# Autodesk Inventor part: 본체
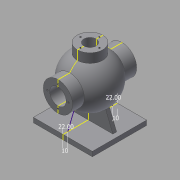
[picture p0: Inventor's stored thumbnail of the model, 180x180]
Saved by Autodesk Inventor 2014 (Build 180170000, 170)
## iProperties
Created: 2015-10
Part Number: 본체
Material: Generic
Document SubType Name: Modeling
Designer: youjin10
Density: 1 g/cm^3
Appearance: Default
Author: youjin10
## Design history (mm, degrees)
sketch "Sketch1"
  geometry: L1 (62.5, -57.5)-(-62.5, -57.5); L2 (-62.5, -57.5)-(-62.5, 57.5); L3 (-62.5, 57.5)-(62.5, 57.5); L4 (62.5, 57.5)-(62.5, -57.5); L5 (62.5, -57.5)-(-62.5, 57.5); L6 (-62.5, -57.5)-(62.5, 57.5); 1 further point
  constraints: 12 end point, 2 midpoint, 2 parallel, 1 horizontal, 1 perpendicular
  dimensions: "d0" = 125 distance of L2.end L3.end; "d1" = 115 distance of L1.end L2.end
extrude "Extrusion1" new body sketch "Sketch1" distance "d2" = 10; taper "d3" = 0 deg
workplane "Work Plane1"
sketch "Sketch4"
  geometry: L1 (0, 53)-(0, -53); L2 (8.646, -43.503)-(8.646, 43.503); A1 r 53 centre (0, 0) between (0, -53) and (0, 53); A2 r 44.354 centre (0, 0) between (8.646, -43.503) and (8.646, 43.503); 2 further points
  constraints: 4 end point, 4 point on circle, 2 centre point, 1 coincident, 1 midpoint, 1 vertical, 1 other
  dimensions: "d9" = 106 distance of L1.start L1.end; "d10" = 53 radius of A1
revolve "Revolution1" stored, may be unused: angle "d11" = 180 deg
workplane "Work Plane2"
sketch "Sketch6"
  geometry: C1 r 31 at (0, 85); 1 further point
  constraints: 1 centre point, 1 vertical alignment
  dimensions: "d13" = 62 diameter of C1; "d14" = 85 distance of point (0, 0) C1.centre
extrude "Extrusion2" join sketch "Sketch6" stored distance "d15" = 10; taper "d16" = 0 deg
mirror "Mirror1"
sketch "Sketch9"
  geometry: C1 r 31 at (0, 0) reference; C2 r 17.5 at (0, 0); 1 further point
  constraints: 1 centre point, 1 coincident
  dimensions: "d20" = 35 diameter of C2
extrude "Extrusion3" cut sketch "Sketch9" distance "d21" = 16; taper "d22" = 0 deg
sketch "Sketch10"
  geometry: C1 r 17.5 at (0, 0) reference; C2 r 18.5 at (0, 0); 1 further point
  constraints: 1 centre point, 1 coincident
  dimensions: "d23" = 37 diameter of C2
extrude "Extrusion4" cut sketch "Sketch10" distance "d24" = 1.75; taper "d25" = 0 deg
sketch "Sketch11"
  geometry: C1 r 18.5 at (0, 0) reference; C2 r 17.5 at (0, 0); 1 further point
  constraints: 1 centre point, 1 coincident
  dimensions: "d26" = 35 diameter of C2
extrude "Extrusion5" cut sketch "Sketch11" stored distance "d27" = 1.75; taper "d28" = 0 deg
workplane "Work Plane3"
sketch "Sketch12"
  geometry: C1 r 27 at (0, 0); 1 further point
  constraints: 1 centre point, 1 coincident
  dimensions: "d30" = 54 diameter of C1
extrude "Extrusion6" join sketch "Sketch12" stored distance "d31" = 1.75; taper "d32" = 0 deg
sketch "Sketch13"
  geometry: C1 r 27 at (0, 0) reference; C2 r 13 at (0, 0)
  constraints: 1 centre point, 1 coincident
  dimensions: "d33" = 26 diameter of C2
extrude "Extrusion7" cut sketch "Sketch13" distance "d34" = 50; taper "d35" = 0 deg
sketch "Sketch14"
  geometry: C1 r 17.5 at (0, 0) reference; C2 r 31 at (0, 0) reference; A1 r 22.5 centre (0, 0) between (0, 22.5) and (-22.5, 0); 3 further points
  constraints: 4 point on circle, 2 horizontal alignment, 2 vertical alignment, 1 centre point, 1 coincident
  dimensions: "d36" = 45 diameter of A1
hole "Hole1" sketch "Sketch14" at (0, 22.5), (-22.5, 0), (0, -22.5), (22.5, 0) diameter "d37" = 3.242; stored, may be unused: countersink angle "d41" = 90 deg, drill point angle "d43" = 118 deg; dims "d38" = 12, "d39" = 4, "d40" = 2, "d42" = 15
sketch "Sketch15"
  geometry: C1 r 17.5 at (0, 0) reference; C2 r 31 at (0, 0) reference; A1 r 24 centre (0, 0) between (0, 24) and (-24, 0); 3 further points
  constraints: 4 point on circle, 2 horizontal alignment, 2 vertical alignment, 1 centre point, 1 coincident
  dimensions: "d44" = 48 diameter of A1
hole "Hole2" sketch "Sketch15" at (0, 24), (-24, 0), (0, -24), (24, 0) diameter "d45" = 3.242; stored, may be unused: countersink angle "d49" = 90 deg, drill point angle "d51" = 118 deg; dims "d46" = 16, "d47" = 4, "d48" = 2, "d50" = 19
sketch "Sketch16"
  geometry: C1 r 13 at (0, 0) reference; C2 r 27 at (0, 0) reference; A1 r 20 centre (0, 0) between (0, 20) and (-20, 0); 2 further points
  constraints: 4 point on circle, 2 horizontal alignment, 2 vertical alignment, 1 centre point, 1 coincident
  dimensions: "d52" = 40 diameter of A1
hole "Hole3" sketch "Sketch16" at (0, 20), (-20, 0), (0, -20), (20, 0) diameter "d53" = 3.242; stored, may be unused: countersink angle "d57" = 90 deg, drill point angle "d59" = 118 deg; dims "d54" = 9, "d55" = 4, "d56" = 2, "d58" = 11
sketch "Sketch17"
  geometry: L1 (4, -4)-(-4, -4); L2 (-4, -4)-(-4, 4); L3 (-4, 4)-(4, 4); L4 (4, 4)-(4, -4); L5 (4, -4)-(-4, 4); L6 (-4, -4)-(4, 4); 1 further point
  constraints: 12 end point, 2 midpoint, 2 parallel, 1 horizontal, 1 perpendicular
  dimensions: "d60" = 8 distance of L2.end L3.end; "d61" = 8 distance of L1.end L2.end
extrude "Extrusion8" join sketch "Sketch17" stored distance "d62" = 50; taper "d63" = 0 deg
workplane "Work Plane4"
workplane "Work Plane5"
sketch "Sketch19"
  geometry: L1 (0, 43)-(0, -43); A1 r 43 centre (0, 0) between (0, -43) and (0, 43); 2 further points
  constraints: 2 end point, 2 point on circle, 1 centre point, 1 coincident, 1 midpoint, 1 vertical
  dimensions: "d66" = 86 distance of L1.start L1.end; "d67" = 43 radius of A1
revolve "Revolution3" sketch "Sketch19" stored, may be unused: angle "d68" = 180 deg
workplane "Work Plane6"
sketch "Sketch20"
  geometry: L1 (62.5, 10)-(-62.5, 10) reference; L2 (-37.379, 47.426)-(-52.5, 10); L3 (-62.5, 0)-(-62.5, 10) reference; L4 (37.379, 47.426)-(52.5, 10); L5 (62.5, 0)-(62.5, 10) reference; A1 r 53 centre (0, 85) between (-27, 130.607) and (27, 130.607) reference; 1 further point
  constraints: 4 end point, 2 point on circle, 2 point on line
  dimensions: "d70" = 10 distance from line of L2.end L3; "d71" = 22 deg angle of L2 L3; "d78" = 10 distance from line of L5 L4.end; "d79" = 22 deg angle of L5 L4
feature "Rib1" dims "d72" = 1, "d73" = 8, "d74" = 0, "d75" = 0, "d76" = 1, "d77" = 1
feature "Rib2" dims "d80" = 1, "d81" = 8, "d82" = 0, "d83" = 0, "d84" = 1, "d85" = 1
sketch "Sketch21"
  geometry: L1 (-52.026, 107.5)-(-53, 109.121) reference; L2 (-53, 109.121)-(-68, 109.121) reference; L3 (-68, 109.121)-(-68, 116) reference; L4 (-68, 116)-(-42.988, 116) reference; L5 (-27, 130.607)-(-27, 150) reference; L6 (-27, 150)-(-21.621, 150) reference; L7 (-21.621, 150)-(-21.621, 139) reference; L8 (-21.621, 139)-(-20, 138.026) reference; L9 (-20, 138.026)-(-18.379, 139) reference; L10 (-18.379, 139)-(-18.379, 150) reference; L11 (-18.379, 150)-(-13, 150) reference; L12 (-13, 150)-(-13, 125.988) reference; L13 (-39.278, 102.5)-(-68, 102.5) reference; L14 (-68, 102.5)-(-68, 105.879) reference; L15 (-68, 105.879)-(-53, 105.879) reference; L16 (-53, 105.879)-(-52.026, 107.5) reference; L17 (50.25, 66.5)-(52, 66.5) reference; L18 (52, 66.5)-(52, 67.5) reference; L19 (52, 67.5)-(68, 67.5) reference; L20 (68, 67.5)-(68, 62.621) reference; L21 (68, 62.621)-(49, 62.621) reference; L22 (49, 62.621)-(48.026, 61) reference; L23 (48.026, 61)-(49, 59.379) reference; L24 (49, 59.379)-(68, 59.379) reference; L25 (68, 59.379)-(68, 54) reference; L26 (68, 54)-(42.988, 54) reference; L27 (4, 32.151)-(4, 10) reference; L28 (4, 10)-(57.5, 10) reference; L29 (57.5, 10)-(57.5, 0) reference; L30 (57.5, 0)-(-57.5, 0) reference; L31 (-57.5, 0)-(-57.5, 10) reference; L32 (-57.5, 10)-(-4, 10) reference; L33 (-4, 10)-(-4, 32.151) reference; L34 (-42.988, 54)-(-68, 54) reference; L35 (-68, 54)-(-68, 60.879) reference; L36 (-68, 60.879)-(-53, 60.879) reference; L37 (-53, 60.879)-(-52.026, 62.5) reference; L38 (-52.026, 62.5)-(-53, 64.121) reference; L39 (-53, 64.121)-(-68, 64.121) reference; L40 (-68, 64.121)-(-68, 67.5) reference; L41 (-68, 67.5)-(-39.278, 67.5) reference; L42 (39.278, 67.5)-(50.25, 67.5) reference; L43 (50.25, 67.5)-(50.25, 66.5) reference; L44 (52, 103.5)-(50.25, 103.5) reference; L45 (50.25, 103.5)-(50.25, 102.5) reference; L46 (50.25, 102.5)-(39.278, 102.5) reference; L47 (13, 125.988)-(13, 150) reference; L48 (13, 150)-(18.379, 150) reference; L49 (18.379, 150)-(18.379, 139) reference; L50 (18.379, 139)-(20, 138.026) reference; L51 (20, 138.026)-(21.621, 139) reference; L52 (21.621, 139)-(21.621, 150) reference; L53 (21.621, 150)-(27, 150) reference; L54 (27, 150)-(27, 130.607) reference; L55 (42.988, 116)-(68, 116) reference; L56 (68, 116)-(68, 110.621) reference; L57 (68, 110.621)-(49, 110.621) reference; L58 (49, 110.621)-(48.026, 109) reference; L59 (48.026, 109)-(49, 107.379) reference; L60 (49, 107.379)-(68, 107.379) reference; L61 (68, 107.379)-(68, 102.5) reference; L62 (68, 102.5)-(52, 102.5) reference; L63 (52, 102.5)-(52, 103.5) reference; L64 (-33.719, 44.109)-(-47.5, 10)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; A1 r 53 centre (0, 85) between (-27, 130.607) and (-42.988, 116) reference; A2 r 43 centre (0, 85) between (-13, 125.988) and (-39.278, 102.5) reference; A3 r 53 centre (0, 85) between (4, 32.151) and (42.988, 54) reference; A4 r 53 centre (0, 85) between (-42.988, 54) and (-4, 32.151) reference; A5 r 43 centre (0, 85) between (-39.278, 67.5) and (0, 42) reference; A6 r 43 centre (0, 85) between (0, 42) and (39.278, 67.5) reference; A7 r 43 centre (0, 85) between (39.278, 102.5) and (13, 125.988) reference; A8 r 53 centre (0, 85) between (42.988, 116) and (27, 130.607) reference; 1 further point
  constraints: 4 end point, 2 point on circle, 2 point on line
  dimensions: "d87" = 22 deg angle of L31 L64; "d88" = 10 distance from line of L31 L64.end; "d89" = 22 deg angle of L29 L65; "d90" = 10 distance from line of L29 L65.end
  node "Project Cut Edges1"
body "Solid1"
other parameters: "d8" = 85, "d12" = -68, "d64" = 0, "d65" = 85, "d69" = 0
